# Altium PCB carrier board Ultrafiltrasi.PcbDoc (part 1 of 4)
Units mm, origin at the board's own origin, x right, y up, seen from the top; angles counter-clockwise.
Board outline 196.34 x 220.85 mm, 2 copper layers (Top Layer, Bottom Layer); 114 components, 209 nets, 667 pads, 70 vias.
Unrouted connection lines stored in the file: 5.
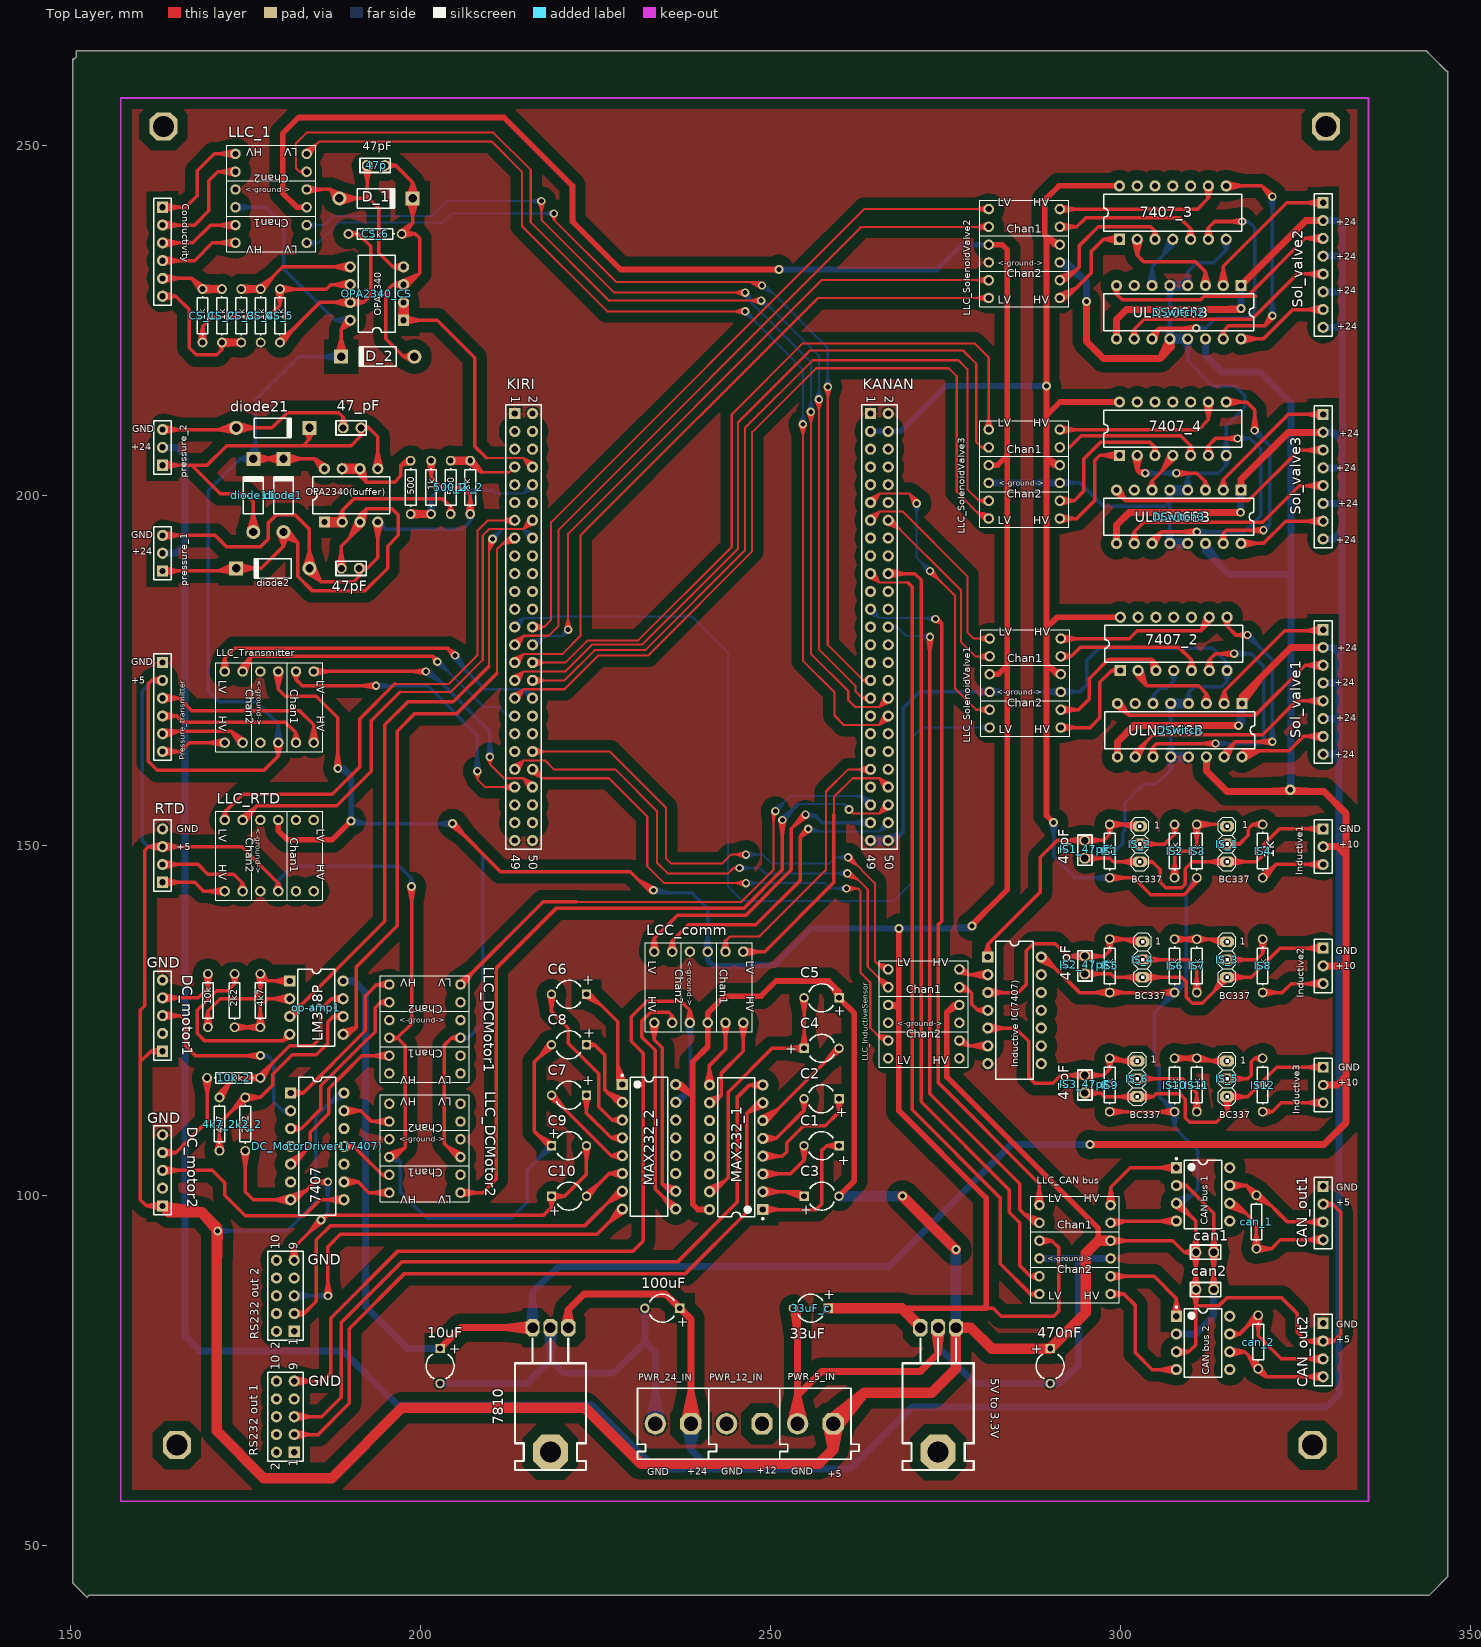
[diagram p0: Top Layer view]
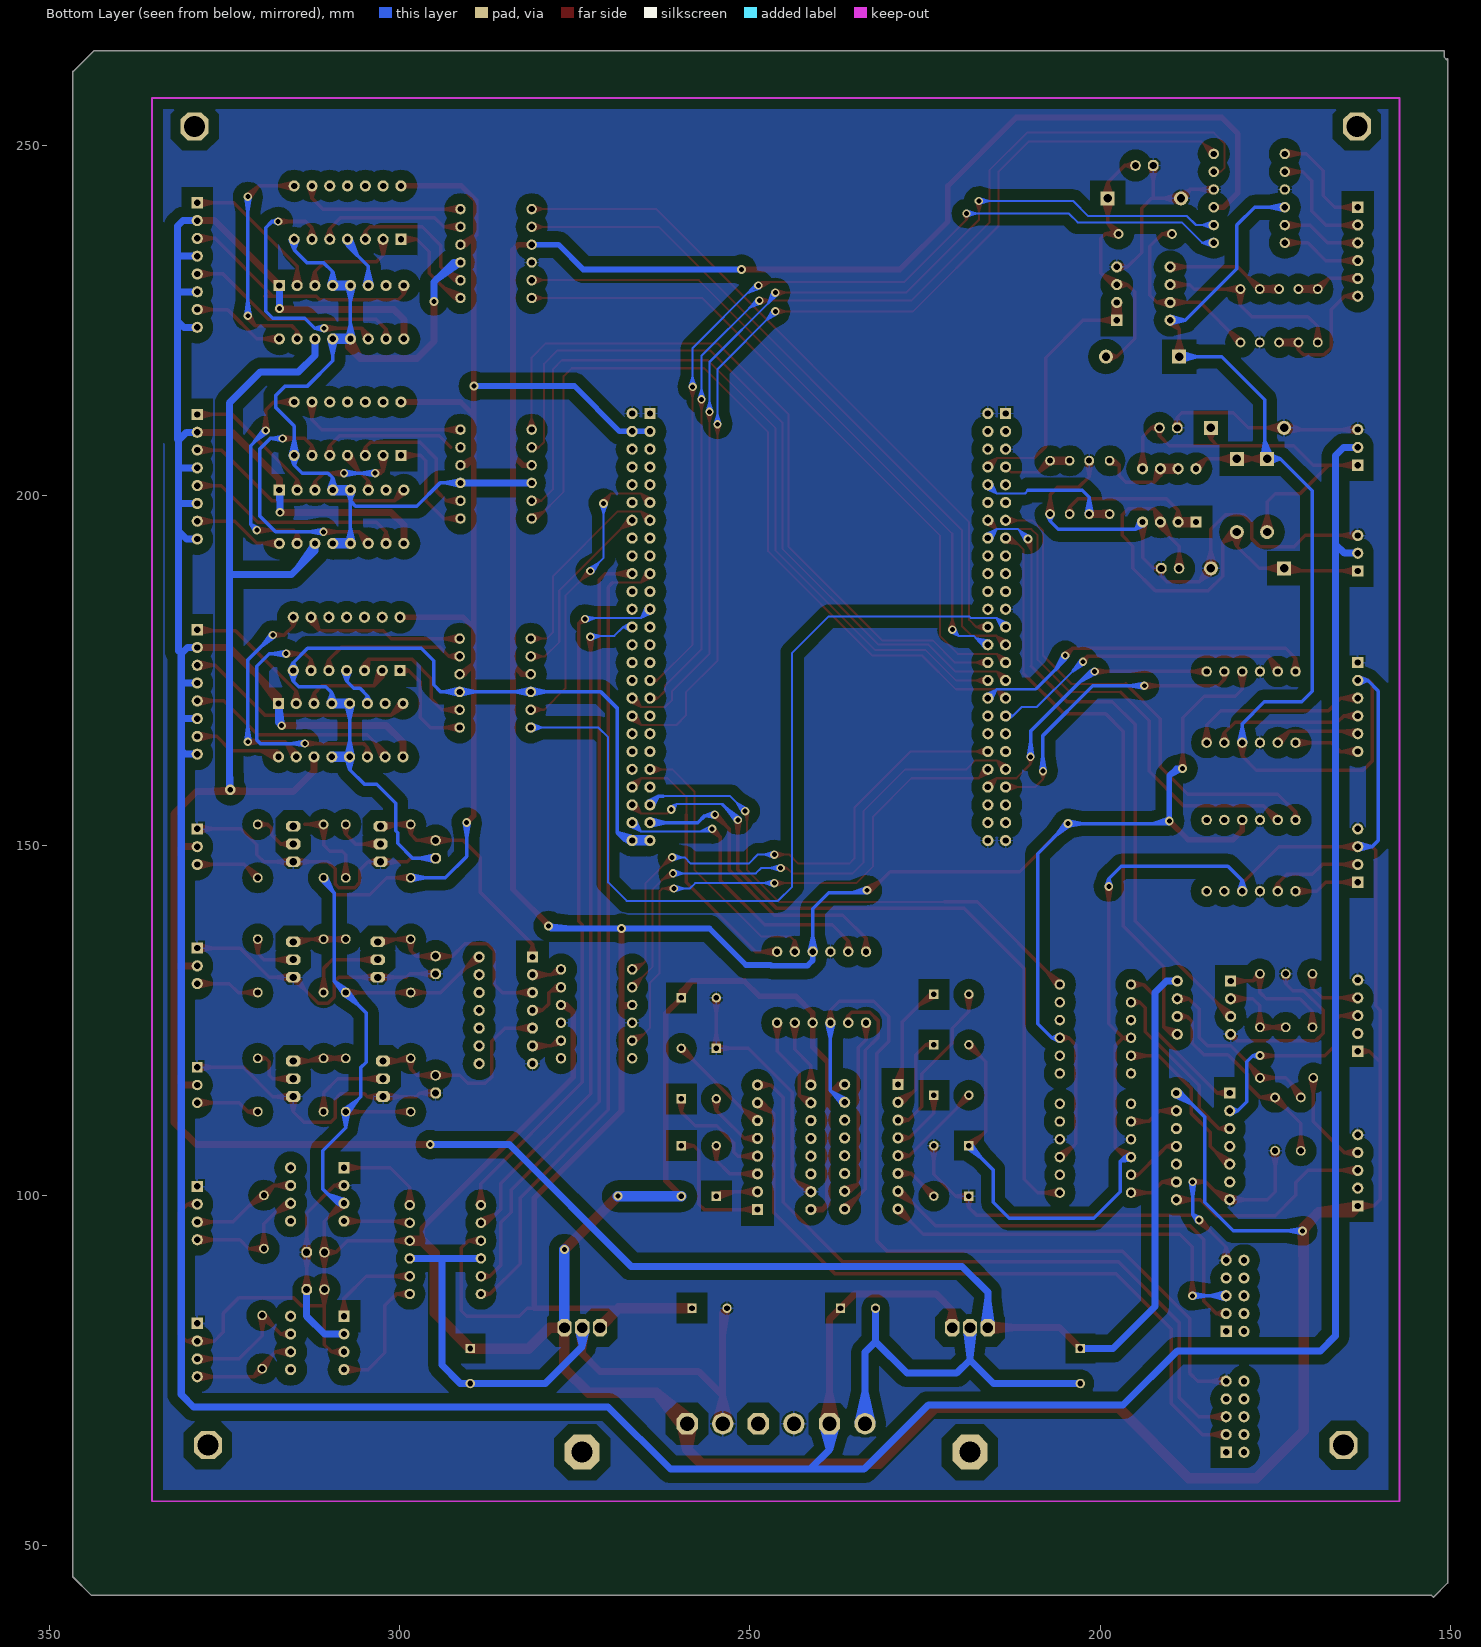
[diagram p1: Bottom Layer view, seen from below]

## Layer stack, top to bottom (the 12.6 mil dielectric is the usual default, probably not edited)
Top Solder: solder mask 0.0102, Solder Resist, Dk 3.5
Top Layer: signal copper 0.0356
Dielectric 1: dielectric 0.32, FR-4, Dk 4.8
Bottom Layer: signal copper 0.0356
Bottom Solder: solder mask 0.0102, Solder Resist, Dk 3.5

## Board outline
150.368,262.382 150.368,44.704 152.4,42.672 152.654,42.926 342.646,42.926 344.043,42.926 346.71,45.593 346.71,260.604 346.583,260.604 344.424,262.763 343.662,263.525 150.876,263.525 150.876,262.636 150.495,262.255

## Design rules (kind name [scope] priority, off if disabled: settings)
Clearance [All] p1: gap=0.3
PolygonConnect [All] p1: connectstyle=Relief reliefconductorwidth=0.254 reliefentries=4 polygonreliefangle="90 Angle" airgapwidth=0.254
RoutingVias [All] p1: holewidth=0.711 width=1.27 viastyle="Through Hole" minholewidth=0.711 minwidth=1.27 maxholewidth=0.711 maxwidth=1.27
SolderMaskExpansion [All] p1: expansion=0.102
Width [All] p1: maxlimit=2 minlimit=0.3 preferedwidth=0.5 minimp=50.000000 maximp=50.000000 favimp=50.000000
29 further rules are at their usual default settings.

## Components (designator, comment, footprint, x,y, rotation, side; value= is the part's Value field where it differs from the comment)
1k "Res1" AXIAL-0.3#1 201.549,201.168 r270 top
1k_2 "1k" AXIAL-0.3#1 207.137,201.168 r90 top
2k2 "Res1" AXIAL-0.3#2 173.482,127.889 r270 top
2k2_2 "2k2" AXIAL-0.3#2 175.006,110.236 r90 top
4k7 "Res1" AXIAL-0.3#2 177.165,127.889 r90 top
4k7_2 "4k7" AXIAL-0.3#2 171.323,110.236 r90 top
"5V to 3.3V" "7805" My_TO-220 276.479,81.153 r180 top
10k "Res1" AXIAL-0.3#2 169.672,127.889 r90 top
10k_2 "10k" AXIAL-0.3#2 173.355,116.84 r180 top
10uF "Cap2" CAPR5-4X5 202.819,75.692 r270 top
33uF_c "33uF" CAPR5-4X5 255.778,83.947 r180 top
47_pF "Cap" My_cap100n 190.246,209.677 r0 top
47p "47pF" My_cap100n 193.675,247.142 r0 top
47pF "Cap" My_cap100n 189.992,189.611 r180 top
100uF "Cap2" CAPR5-4X5 234.569,83.947 r180 top
470nF "Cap2" CAPR5-4X5 289.941,75.692 r270 top
500 "Res1" AXIAL-0.3#1 198.628,201.168 r90 top
500_2 "500" AXIAL-0.3#1 204.343,201.168 r270 top
7407_2 "7407" 646-06 307.594,178.816 r0 top
7407_3 "7407" 646-06 307.467,240.411 r0 top
7407_4 "7407" 646-06 307.467,209.55 r0 top
7810 "7805" My_TO-220 221.107,81.153 r180 top
C1 "Cap2" CAPR5-4X5 257.302,107.156 r180 top
C2 "Cap2" CAPR5-4X5 257.302,113.855 r180 top
C3 "Cap2" CAPR5-4X5 257.302,99.949 r0 top
C4 "Cap2" CAPR5-4X5 257.302,121.063 r0 top
C5 "Cap2" CAPR5-4X5 257.302,128.27 r180 top
C6 "Cap2" CAPR5-4X5 221.234,128.778 r180 top
C7 "Cap2" CAPR5-4X5 221.234,114.364 r180 top
C8 "Cap2" CAPR5-4X5 221.234,121.571 r180 top
C9 "Cap2" CAPR5-4X5 221.234,107.156 r0 top
C10 "Cap2" CAPR5-4X5 221.234,99.949 r0 top
can1 "Cap" My_cap100n 312.039,91.948 r180 top
can2 "Cap" My_cap100n 312.039,86.614 r180 top
"CAN bus 1" "MCP2551-I/P" PDIP300-P8 311.785,100.203 r0 top
"CAN bus 2" "MCP2551-I/P" PDIP300-P8 311.785,78.994 r0 top
can_1 "Res1" AXIAL-0.3#2 319.405,96.266 r90 top
can_2 "Res1" AXIAL-0.3#2 319.659,79.121 r90 top
CAN_out1 "Header 4" HDR1X4 328.93,101.346 r270 top
CAN_out2 "Header 4" HDR1X4 328.93,81.788 r270 top
Conductivity "Header 6" HDR1X6 163.195,241.173 r270 top
CS_1 "1k" AXIAL-0.3#2 168.91,225.679 r270 top
CS_2 "1k" AXIAL-0.3#2 171.672,225.679 r90 top
CS_3 "1k" AXIAL-0.3#2 174.434,225.679 r90 top
CS_4 "1k" AXIAL-0.3#2 177.197,225.679 r90 top
CS_5 "1k" AXIAL-0.3#2 179.959,225.679 r270 top
CS_6 "1k" AXIAL-0.3#2 193.548,237.363 r0 top
D_1 "1N4001" DO-41 193.675,242.443 r0 top
D_2 "1N4001" DO-41 193.929,219.837 r180 top
DC_motor1 "Header 5" HDR1X5 163.195,120.65 r90 top
DC_motor2 "Header 5" HDR1X5 163.195,98.552 r90 top
DC_MotorDriver1(7407) "7407" 646-06 185.293,107.061 r270 top
diode1 "1N4001" DO-41 180.467,200.025 r90 top
diode2 "1N4001" DO-41 178.943,189.611 r180 top
diode11 "1N4001" DO-41 176.149,200.025 r90 top
diode21 "1N4001" DO-41 178.943,209.677 r0 top
DSwitch "ULN2068B" 648C-02 308.444,166.497 r180 top
DSwitch2 "ULN2068B" 648C-02 308.317,226.187 r180 top
DSwitch3 "ULN2068B" 648C-02 308.317,196.977 r180 top
Inductive1 "Header 3" HDR1X3#1 328.93,152.4 r270 top
Inductive2 "Header 3" HDR1X3#1 328.93,135.382 r270 top
Inductive3 "Header 3" HDR1X3#2 328.93,118.364 r270 top
"Inductive IC(7407)" "SN74LS14N" 646-06 284.861,126.492 r270 top
IS1 "1k" AXIAL-0.3#2 298.45,149.225 r90 top
IS1_47pF "47pF" My_cap100n 294.894,149.479 r90 top
IS2 "1k" AXIAL-0.3#2 307.721,149.225 r270 top
IS2_47pF "47pF" My_cap100n 294.894,132.969 r90 top
IS3 "1k" AXIAL-0.3#2 310.896,149.225 r90 top
IS3_47pF "47pF" My_cap100n 294.894,115.951 r90 top
IS4 "1k" AXIAL-0.3#2 320.294,149.225 r270 top
IS5 "1k" AXIAL-0.3#2 298.45,132.842 r90 top
IS6 "1k" AXIAL-0.3#2 307.721,132.842 r90 top
IS7 "1k" AXIAL-0.3#2 310.896,132.842 r90 top
IS8 "1k" AXIAL-0.3#2 320.294,132.842 r270 top
IS9 "1k" AXIAL-0.3#2 298.45,115.824 r90 top
IS10 "1k" AXIAL-0.3#2 307.721,115.824 r90 top
IS11 "1k" AXIAL-0.3#2 310.896,115.824 r90 top
IS12 "1k" AXIAL-0.3#2 320.294,115.824 r270 top
IS_1 "BC337" My_1X03 315.214,150.241 r270 top
IS_2 "BC337" My_1X03 302.768,150.241 r270 top
IS_3 "BC337" My_1X03 315.214,133.731 r270 top
IS_4 "BC337" My_1X03 303.149,133.731 r270 top
IS_5 "BC337" My_1X03 315.214,116.713 r270 top
IS_6 "BC337" My_1X03 302.387,116.713 r270 top
KANAN "KANAN" HDR2X25 264.287,211.709 r270 top
KIRI "KIRI" HDR2X25 213.487,211.709 r270 top
LCC_comm "Logic Level Converter (3.3v - 5v) /  /  / https://www.sparkfun.com/products/8745" LOGIC_LEVEL_CONVERTER 232.156,136.144 r270 top
LLC_1 "Logic Level Converter (3.3v - 5v) /  /  / https://www.sparkfun.com/products/8745" LOGIC_LEVEL_CONVERTER 185.039,250.063 r180 top
"LLC_CAN bus" "Logic Level Converter (3.3v - 5v) /  /  / https://www.sparkfun.com/products/8745" LOGIC_LEVEL_CONVERTER 287.147,84.709 r0 top
LLC_DCMotor1 "Logic Level Converter (3.3v - 5v) /  /  / https://www.sparkfun.com/products/8745" LOGIC_LEVEL_CONVERTER 207.01,131.445 r180 top
LLC_DCMotor2 "Logic Level Converter (3.3v - 5v) /  /  / https://www.sparkfun.com/products/8745" LOGIC_LEVEL_CONVERTER 207.01,114.427 r180 top
LLC_InductiveSensor "Logic Level Converter (3.3v - 5v) /  /  / https://www.sparkfun.com/products/8745" LOGIC_LEVEL_CONVERTER 265.557,118.364 r0 top
LLC_RTD "Logic Level Converter (3.3v - 5v) /  /  / https://www.sparkfun.com/products/8745" LOGIC_LEVEL_CONVERTER 170.815,154.94 r270 top
LLC_SolenoidValve1 "Logic Level Converter (3.3v - 5v) /  /  / https://www.sparkfun.com/products/8745" LOGIC_LEVEL_CONVERTER 280.035,165.608 r0 top
LLC_SolenoidValve2 "Logic Level Converter (3.3v - 5v) /  /  / https://www.sparkfun.com/products/8745" LOGIC_LEVEL_CONVERTER 279.908,226.949 r0 top
LLC_SolenoidValve3 "Logic Level Converter (3.3v - 5v) /  /  / https://www.sparkfun.com/products/8745" LOGIC_LEVEL_CONVERTER 279.908,195.453 r0 top
LLC_Transmitter "Logic Level Converter (3.3v - 5v) /  /  / https://www.sparkfun.com/products/8745" LOGIC_LEVEL_CONVERTER 170.815,176.149 r270 top
MAX232_1 "MAX232ACPE" PE16A 245.11,106.934 r180 top
MAX232_2 "MAX232ACPE" PE16A 232.664,107.002 r0 top
op-amp1 "LM358P" P008 185.166,126.873 r270 top
OPA2340(buffer) "LM358P" P008 190.119,200.025 r0 top
OPA2340_CS "OPA2340" P008 193.802,228.854 r90 top
pressure_1 "Header 3" HDR1X3#1 163.195,189.23 r90 top
pressure_2 "Header 3" HDR1X3#1 163.195,204.343 r90 top
Pressure_transmitter "Header 6" HDR1X6 163.195,176.149 r270 top
PWR_5_IN "CON2 pin blue" My_CN2 261.493,62.357 r180 top
PWR_12_IN "CON2 pin blue" My_CN2 251.333,62.357 r180 top
PWR_24_IN "CON2 pin blue" My_CN2 241.173,62.357 r180 top
"RS232 out 1" "Header 5X2" HDR2X5 181.991,63.373 r90 top
"RS232 out 2" "Header 5X2" HDR2X5 181.991,80.645 r90 top
RTD "Header 4" HDR1X4 163.195,144.78 r90 top
Sol_valve1 "Header 8" HDR1X8 328.93,180.848 r270 top
Sol_valve2 "Header 8" HDR1X8 328.93,241.808 r270 top
Sol_valve3 "Header 8" HDR1X8 328.93,211.582 r270 top

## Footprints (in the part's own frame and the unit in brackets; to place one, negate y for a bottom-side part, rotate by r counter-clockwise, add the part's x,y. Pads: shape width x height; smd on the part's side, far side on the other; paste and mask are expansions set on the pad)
646-06 [mm] "DIP; 14 Leads; Row Spacing 7.62 mm; Pitch 2.54 mm"
  rect 1.6x1.6 hole 0.9 mask+0.102: 1(-7.62,-3.81)
  round 1.6 hole 0.9 mask+0.102: 2(-5.08,-3.81) 3(-2.54,-3.81) 4(0,-3.81) 5(2.54,-3.81) 6(5.08,-3.81) 7(7.62,-3.81) 8(7.62,3.81) 9(5.08,3.81) 10(2.54,3.81) 11(0,3.81) 12(-2.54,3.81) 13(-5.08,3.81) 14(-7.62,3.81)
  silkscreen extent -9.85,-2.65 9.85,2.65
648C-02 [mm] "DIP; 16 Leads; Row Spacing 7.62 mm; Pitch 2.54 mm"
  rect 1.6x1.6 hole 0.9 mask+0.102: 1(-8.89,-3.81)
  round 1.6 hole 0.9 mask+0.102: 2(-6.35,-3.81) 3(-3.81,-3.81) 4(-1.27,-3.81) 5(1.27,-3.81) 6(3.81,-3.81) 7(6.35,-3.81) 8(8.89,-3.81) 9(8.89,3.81) 10(6.35,3.81) 11(3.81,3.81) 12(1.27,3.81) 13(-1.27,3.81) 14(-3.81,3.81) 15(-6.35,3.81) 16(-8.89,3.81)
  silkscreen extent -10.7,-2.65 10.7,2.65
AXIAL-0.3#1 [mm] "Axial Device, Thru-Hole; 2 Leads; 0.3 in Pin Spacing"
  round 1.4 hole 0.85: 1(-3.81,0) 2(3.81,0)
  silkscreen extent -2.77,-0.76 2.77,0.76
AXIAL-0.3#2 [mm] "Axial Device, Thru-Hole; 2 Leads; 0.3 in Pin Spacing"
  round 1.4 hole 0.9: 1(-3.81,0) 2(3.81,0)
  silkscreen extent -2.77,-0.76 2.77,0.76
CAPR5-4X5 [mm] "Capacitor; 2 Leads"
  rect 1.35x1.35 hole 0.8: 1(-2.5,0)
  round 1.35 hole 0.8: 2(2.5,0)
  silkscreen extent -1.69,-2 1.82,2
DO-41 [mm] "Diode, Axial; Body 5.2 x 2.7 mm (LxDia. max), Lead Dia. 0.86 mm (max)"
  round 2 hole 1.2: 1(-5.23,0)
  rect 2x2 hole 1.2: 2(5.23,0)
  silkscreen extent -2.65,-1.4 2.75,1.4
HDR1X3#1 [mm] "Connector; Header; 3 Position"
  rect 1.6x1.6 hole 0.9 mask+0.102: 1(0,0)
  round 1.6 hole 0.9 mask+0.102: 2(2.54,0) 3(5.08,0)
  silkscreen extent -1.27,-1.27 6.35,1.27
HDR1X3#2 [mm] "Connector; Header; 3 Position"
  rect 1.5x1.5 hole 0.9: 1(0,0)
  round 1.5 hole 0.9: 2(2.54,0) 3(5.08,0)
  silkscreen extent -1.27,-1.27 6.35,1.27
HDR1X4 [mm] "Connector; Header; 4 Position"
  rect 1.6x1.6 hole 0.9 mask+0.102: 1(0,0)
  round 1.6 hole 0.9 mask+0.102: 2(2.54,0) 3(5.08,0) 4(7.62,0)
  silkscreen extent -1.27,-1.27 8.89,1.27
HDR1X5 [mm] "Connector; Header; 5 Position"
  rect 1.6x1.6 hole 0.9 mask+0.102: 1(0,0)
  round 1.6 hole 0.9 mask+0.102: 2(2.54,0) 3(5.08,0) 4(7.62,0) 5(10.16,0)
  silkscreen extent -1.27,-1.27 11.43,1.27
HDR1X6 [mm] "Connector; Header; 6 Position"
  rect 1.6x1.6 hole 0.9 mask+0.102: 1(0,0)
  round 1.6 hole 0.9 mask+0.102: 2(2.54,0) 3(5.08,0) 4(7.62,0) 5(10.16,0) 6(12.7,0)
  silkscreen extent -1.27,-1.27 13.97,1.27
HDR1X8 [mm] "Connector; Header; 8 Position"
  rect 1.6x1.6 hole 0.9 mask+0.102: 1(0,0)
  round 1.6 hole 0.9 mask+0.102: 2(2.54,0) 3(5.08,0) 4(7.62,0) 5(10.16,0) 6(12.7,0) 7(15.24,0) 8(17.78,0)
  silkscreen extent -1.27,-1.27 19.05,1.27
HDR2X5 [mm] "Connector; Header; 5x2 Position"
  rect 1.6x1.6 hole 0.9 mask+0.102: 1(0,0)
  round 1.6 hole 0.9 mask+0.102: 2(0,2.54) 3(2.54,0) 4(2.54,2.54) 5(5.08,0) 6(5.08,2.54) 7(7.62,0) 8(7.62,2.54) 9(10.16,0) 10(10.16,2.54)
  silkscreen extent -1.27,-1.27 11.43,3.81
HDR2X25 [mm] "Connector; Header; 25x2 Position"
  rect 1.6x1.6 hole 0.9 mask+0.102: 1(0,0)
  round 1.6 hole 0.9 mask+0.102: 2(0,2.54) 3(2.54,0) 4(2.54,2.54) 5(5.08,0) 6(5.08,2.54) 7(7.62,0) 8(7.62,2.54) 9(10.16,0) 10(10.16,2.54) 11(12.7,0) 12(12.7,2.54) 13(15.24,0) 14(15.24,2.54) 15(17.78,0) 16(17.78,2.54) 17(20.32,0) 18(20.32,2.54) 19(22.86,0) 20(22.86,2.54) 21(25.4,0) 22(25.4,2.54) 23(27.94,0) 24(27.94,2.54) 25(30.48,0) 26(30.48,2.54) 27(33.02,0) 28(33.02,2.54) 29(35.56,0) 30(35.56,2.54) 31(38.1,0) 32(38.1,2.54) 33(40.64,0) 34(40.64,2.54) 35(43.18,0) 36(43.18,2.54) 37(45.72,0) 38(45.72,2.54) 39(48.26,0) 40(48.26,2.54) 41(50.8,0) 42(50.8,2.54) 43(53.34,0) 44(53.34,2.54) 45(55.88,0) 46(55.88,2.54) 47(58.42,0) 48(58.42,2.54) 49(60.96,0) 50(60.96,2.54)
  silkscreen extent -1.27,-1.27 62.23,3.81
LOGIC_LEVEL_CONVERTER [mm]
  round 1.5 hole 0.9: P$1(1.27,13.97) P$2(1.27,11.43) P$3(1.27,8.89) P$4(1.27,6.35) P$5(1.27,3.81) P$6(1.27,1.27) P$7(11.43,1.27) P$8(11.43,3.81) P$9(11.43,6.35) P$10(11.43,8.89) P$11(11.43,11.43) P$12(11.43,13.97)
  silkscreen extent 0,0 12.7,15.24
My_1X03 [mil]
  oct 60x80 hole 40: 1(-100,0) 2(0,0) 3(100,0)
  silkscreen extent -150,-50 150,50
My_cap100n [mil]
  oct 60x60 hole 40: 1(-50,0)
  round 60 hole 40: 2(50,0)
  silkscreen extent -90,-40 80,40
My_CN2 [mil]
  oct 120x120 hole 80: 1(99.5,-200.5)
  round 120 hole 80: 2(299.5,-200.5)
  silkscreen extent -45,-400 400,0
My_TO-220 [mil]
  oct 196.85x196.85 hole 118.11: 0(99.49,699.49)
  oct 80x100 hole 60: 1(-0.5,-0.5) 2(99.5,-0.5) 3(199.5,-0.5)
  silkscreen extent -101,60 300,800
P008 [mm] "DIP; 8 Leads; Row Spacing 7.62 mm; Pitch 2.54 mm"
  rect 1.6x1.6 hole 0.9 mask+0.102: 1(-3.81,-3.81)
  round 1.6 hole 0.9 mask+0.102: 2(-1.27,-3.81) 3(1.27,-3.81) 4(3.81,-3.81) 5(3.81,3.81) 6(1.27,3.81) 7(-1.27,3.81) 8(-3.81,3.81)
  silkscreen extent -5.5,-2.65 5.5,2.65
PDIP300-P8 [mm] "DIP, 8-Leads, Row Spacing 7.62mm, Pitch 2.54mm, Body 9.5x6.6mm"
  rect 1.6x1.6 hole 0.9 mask+0.102: 1(-3.81,3.81)
  round 1.6 hole 0.9 mask+0.102: 2(-3.81,1.27) 3(-3.81,-1.27) 4(-3.81,-3.81) 5(3.81,-3.81) 6(3.81,-1.27) 7(3.81,1.27) 8(3.81,3.81)
  silkscreen extent -3.93,-4.9 2.65,5.23, body extent -3.55,-4.9 3.55,4.9, height 5.34
PE16A [mm] "DIP, 16-Leads, Row Spacing 7.62mm, Pitch 2.54mm, Body 19.18x6.99mm"
  rect 1.6x1.6 hole 0.9 mask+0.102: 1(-3.81,8.89)
  round 1.6 hole 0.9 mask+0.102: 2(-3.81,6.35) 3(-3.81,3.81) 4(-3.81,1.27) 5(-3.81,-1.27) 6(-3.81,-3.81) 7(-3.81,-6.35) 8(-3.81,-8.89) 9(3.81,-8.89) 10(3.81,-6.35) 11(3.81,-3.81) 12(3.81,-1.27) 13(3.81,1.27) 14(3.81,3.81) 15(3.81,6.35) 16(3.81,8.89)
  silkscreen extent -3.94,-9.9 2.65,10.31, body extent -3.3,-9.9 3.3,9.9, height 5.08

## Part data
1k 2k2 4k7 10k 500 can_1 can_2: "Resistor"
1k_2 2k2_2 4k7_2 10k_2 500_2 CS_1 CS_2 CS_3 CS_4 CS_5 CS_6 IS1 IS2 IS3 IS4 IS5 IS6 IS7 IS8 IS9 IS10 IS11 IS12: library part Res1, "Resistor"
"5V to 3.3V" 7810: "Regulator"
10uF 100uF 470nF C1 C2 C3 C4 C5 C6 C7 C8 C9 C10: "Capacitor"
33uF_c: library part Cap2, "Capacitor"
47_pF 47p 47pF can1 can2 IS1_47pF IS2_47pF IS3_47pF: library part "Cap ceramic", "CAP-100Nf"
7407_2 7407_3 7407_4 DC_MotorDriver1(7407): library part SN74LS14N, "Hex Schmitt-Trigger Inverter"
"CAN bus 1" "CAN bus 2": "High-Speed CAN Transceiver, 8-Pin PDIP, Industrial Temperature"
CAN_out1 CAN_out2 RTD: "Header, 4-Pin"
Conductivity Pressure_transmitter: "Header, 6-Pin"
D_1 D_2 diode1 diode2 diode11 diode21: library part "Diode 1N4001", "1 Amp General Purpose Rectifier"
DC_motor1 DC_motor2: "Header, 5-Pin"
DSwitch DSwitch2 DSwitch3: "Quad 1.5A Darlington Switch"
Inductive1 Inductive2 Inductive3 pressure_1 pressure_2: "Header, 3-Pin"
"Inductive IC(7407)": "Hex Schmitt-Trigger Inverter"
IS_1 IS_2 IS_3 IS_4 IS_5 IS_6: "Transistor, NPN, 300MHz, 40V, 200mA, SOT-23 pkg"
KANAN KIRI: library part "Header 25X2", "Header, 25-Pin, Dual row"
LCC_comm LLC_1 "LLC_CAN bus" LLC_DCMotor1 LLC_DCMotor2 LLC_InductiveSensor LLC_RTD LLC_SolenoidValve1 LLC_SolenoidValve2 LLC_SolenoidValve3 LLC_Transmitter: library part LOGIC_LEVEL_CONVERTER
MAX232_1 MAX232_2: "+5V Powered, Multi-Channel RS-232 Driver/Receiver"
op-amp1 OPA2340(buffer): "Dual Operational Amplifier"
OPA2340_CS: library part LM358P, "Dual Operational Amplifier"
PWR_5_IN PWR_12_IN PWR_24_IN: "Connector blue screw"
"RS232 out 1" "RS232 out 2": "Header, 5-Pin, Dual row"
Sol_valve1 Sol_valve2 Sol_valve3: "Header, 8-Pin"

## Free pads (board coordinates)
  oct 4x4 hole 3: 0(329.311,252.73) 1(163.322,252.73) 2(165.227,64.389) 3(327.406,64.389)

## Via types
v1: diameter 1.2, hole 0.711, Top Layer to Bottom Layer, 26 vias
v2: diameter 1.27, hole 0.711, Top Layer to Bottom Layer, 24 vias
v3: diameter 1.2, hole 0.7, Top Layer to Bottom Layer, 19 vias
v4: diameter 1.5, hole 0.8, Top Layer to Bottom Layer, 1 vias

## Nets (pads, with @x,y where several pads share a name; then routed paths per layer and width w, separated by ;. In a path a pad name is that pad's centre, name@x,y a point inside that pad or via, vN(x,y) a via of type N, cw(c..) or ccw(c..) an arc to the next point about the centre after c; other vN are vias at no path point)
DINPLC1: Conductivity.4 LLC_1.P$12 | length 20.6
  Top Layer w0.5: Conductivity.4@163.195,233.553 167.767,233.553 170.307,236.093 LLC_1.P$12@173.609,236.093 ; Conductivity.4@163.261,233.007 165.495,233.553 Conductivity.4@163.261,234.099 ; LLC_1.P$12@173.553,235.596 171.359,236.093 LLC_1.P$12@173.553,236.59
DOPLC1: Conductivity.1 LLC_1.P$7 | length 24.8
  Top Layer w0.5: Conductivity.1@163.195,241.173 166.497,241.173 168.148,242.824 168.148,246.38 170.561,248.793 LLC_1.P$7@173.609,248.793 ; Conductivity.1@163.261,240.627 165.495,241.173 Conductivity.1@163.261,241.719 ; LLC_1.P$7@173.553,248.296 171.359,248.793 LLC_1.P$7@173.553,249.29
DOPLC2: Conductivity.2 LLC_1.P$8 | length 27.4
  Top Layer w0.5: Conductivity.2@163.195,238.633 167.767,238.633 169.799,240.665 169.799,244.983 171.069,246.253 LLC_1.P$8@173.609,246.253 171.359,246.253 ; Conductivity.2@163.261,238.087 165.495,238.633 Conductivity.2@163.261,239.179 ; LLC_1.P$8@173.553,245.756 171.359,246.253 ; LLC_1.P$8@173.553,246.75 171.359,246.253
DOPLC3: Conductivity.3 LLC_1.P$11 | length 20.6
  Top Layer w0.5: Conductivity.3@163.195,236.093 167.513,236.093 170.053,238.633 LLC_1.P$11@173.609,238.633 ; Conductivity.3@163.261,235.547 165.495,236.093 Conductivity.3@163.261,236.639 ; LLC_1.P$11@173.553,238.136 171.359,238.633 LLC_1.P$11@173.553,239.13
DTR_5V: LLC_Transmitter.P$11 Pressure_transmitter.4 | length 28.3
  Top Layer w0.5: Pressure_transmitter.4@163.195,168.529 165.227,168.529 ; Pressure_transmitter.4@163.269,167.984 165.227,168.529 ; Pressure_transmitter.4@163.269,169.074 165.227,168.529 ; LLC_Transmitter.P$11@181.753,164.808 182.245,166.116 ; LLC_Transmitter.P$11@182.245,164.719 182.245,166.116 ; LLC_Transmitter.P$11@182.737,164.808 182.245,166.116 ; 165.227,168.529 166.116,167.64 180.721,167.64 182.245,166.116
GND: 1k.1 1k_2.1 2k2.1 2k2_2.1 10uF.2 33uF_c.2 47_pF.1 47p.1 47pF.1 100uF.2 470nF.2 7407_2.7 7407_3.7 7407_4.7 7810.2 "5V to 3.3V.2" "CAN bus 1.2" "CAN bus 2.2" "Inductive IC(7407).7" "LLC_CAN bus.P$4" "LLC_CAN bus.P$9" "RS232 out 1.9" "RS232 out 2.9" C4.1 C5.2 C9.2 C10.1 can1.1 can2.1 CAN_out1.1 CAN_out2.1 CS_4.1 D_1.1 DC_motor1.5 DC_motor2.5 DC_MotorDriver1(7407).7 diode2.1 diode21.1 DSwitch2.4 DSwitch2.5 DSwitch2.12 DSwitch2.13 DSwitch3.4 DSwitch3.5 DSwitch3.12 DSwitch3.13 DSwitch.4 DSwitch.5 DSwitch.12 DSwitch.13 Inductive1.1 Inductive2.1 Inductive3.1 IS1_47pF.1 IS2_47pF.1 IS3_47pF.1 IS_1.3 IS_2.3 IS_3.3 IS_4.3 IS_5.3 IS_6.3 KANAN.1 KANAN.2 KANAN.49 KANAN.50 KIRI.1 KIRI.2 KIRI.5 KIRI.23 KIRI.49 KIRI.50 LCC_comm.P$4 LCC_comm.P$9 LLC_1.P$4 LLC_1.P$9 LLC_DCMotor2.P$4 LLC_DCMotor2.P$9 LLC_InductiveSensor.P$4 LLC_InductiveSensor.P$9 LLC_RTD.P$4 LLC_RTD.P$9 LLC_SolenoidValve1.P$4 LLC_SolenoidValve1.P$9 LLC_SolenoidValve2.P$4 LLC_SolenoidValve2.P$9 LLC_SolenoidValve3.P$4 LLC_SolenoidValve3.P$9 LLC_Transmitter.P$4 LLC_Transmitter.P$9 MAX232_1.15 MAX232_2.15 op-amp1.4 OPA2340(buffer).4 OPA2340_CS.4 pressure_1.3 pressure_2.3 Pressure_transmitter.1 PWR_5_IN.2 PWR_12_IN.2 PWR_24_IN.2 RTD.4 | length 1609.2
  Top Layer w0.5: pressure_1.3@163.195,194.31 170.688,194.31 172.339,192.659 177.165,192.659 178.308,193.802 178.308,196.088 179.451,197.231 182.118,197.231 184.173,195.176 diode2.1@184.173,189.611 ; pressure_2.3@163.195,209.423 173.482,209.423 173.736,209.677 178.816,209.677 180.975,211.836 188.341,211.836 188.976,211.201 ; pressure_1.3@163.261,193.764 165.495,194.31 pressure_1.3@163.261,194.856 ; pressure_2.3@163.261,208.877 165.495,209.423 pressure_2.3@163.261,209.969 ; 2k2.1@173.038,131.627 173.482,130.302 ; 2k2.1@173.482,131.699 173.482,130.302 ; diode21.1@173.529,210.404 171.179,209.423 ; diode21.1@173.676,209.924 171.179,209.423 ; diode21.1@173.677,208.928 171.179,209.423 ; diode21.1@173.725,209.927 176.213,209.677 ; diode21.1@173.825,208.935 176.213,209.677 ; diode21.1@173.825,210.419 176.213,209.677 ; 2k2.1@173.926,131.627 173.482,130.302 ; 2k2_2.1@174.558,106.38 175.006,104.226 2k2_2.1@175.454,106.38 ; 2k2_2.1@175.006,106.426 175.006,100.584 176.149,99.441 181.483,99.441 ; op-amp1.4@180.891,123.357 180.467,122.174 ; 181.246,99.937 183.763,100.832 ; 181.417,98.895 179.183,99.441 181.417,99.987 ; 181.447,90.886 181.991,92.672 ; op-amp1.4@181.65,122.598 180.467,122.174 ; 181.816,99.003 183.763,100.832 ; 181.991,73.533 186.055,73.533 187.222,74.7 187.222,82.536 196.737,92.051 230.354,92.051 231.857,93.554 231.857,120.351 230.148,122.061 230.148,125.589 232.321,127.762 237.236,127.762 238.506,126.492 ; 181.991,90.805 181.991,92.672 ; 182.057,72.987 184.291,73.533 182.057,74.079 ; 182.535,90.886 181.991,92.672 ; diode2.1@183.431,189.724 184.173,192.111 ; diode2.1@183.682,189.044 185.801,187.706 ; LLC_1.P$4@183.769,243.713 187.198,243.713 187.186,243.701 ; LLC_1.P$4@183.825,243.216 186.019,243.713 LLC_1.P$4@183.825,244.21 ; diode2.1@183.923,189.623 184.173,192.111 ; diode2.1@183.991,189.439 185.801,187.706 ; diode2.1@184.371,189.764 185.801,187.706 ; diode2.1@184.423,189.623 184.173,192.111 ; diode2.1@184.81,190.007 185.801,187.706 ; diode2.1@184.915,189.724 184.173,192.111 ; v2@185.545,96.77 184.143,94.824 ; v2@185.621,96.838 186.577,97.258 ; v2(185.839,96.52) 184.143,94.824 ; v2@186.088,96.227 184.143,94.824 ; v2@186.156,96.303 186.577,97.258 ; v3@186.759,101.633 184.912,101.981 ; v3@186.759,102.329 184.912,101.981 ; v3(186.792,101.981) 184.912,101.981 ; D_1.1@187.815,242.036 187.186,243.701 ; D_1.1@188.256,242.279 187.186,243.701 ; D_1.1@188.457,242.193 190.945,242.443 ; D_1.1@188.457,242.693 190.945,242.443 ; 47_pF.1@188.471,209.763 188.976,211.201 ; D_1.1@188.557,241.701 190.945,242.443 ; D_1.1@188.557,243.185 190.945,242.443 ; D_1.1@188.609,242.632 187.186,243.701 ; D_1.1@188.852,243.073 187.186,243.701 ; 47_pF.1@188.976,209.677 188.976,211.201 ; 47_pF.1@189.481,209.763 188.976,211.201 ; 47pF.1@190.763,189.496 191.262,188.468 ; 47pF.1@191.377,189.112 192.405,189.611 ; 47pF.1@191.377,190.11 192.405,189.611 ; 47pF.1@191.761,189.496 191.262,188.468 ; 47p.1@191.896,247.084 192.405,244.88 47p.1@192.914,247.084 ; 47p.1@192.405,247.142 192.405,242.697 192.659,242.443 ; 193.383,196.149 193.929,193.915 194.475,196.149 ; 193.929,196.215 193.929,191.135 192.405,189.611 ; OPA2340_CS.4@197.513,232.123 196.088,232.664 ; OPA2340_CS.4@197.513,233.205 196.088,232.664 ; OPA2340_CS.4@197.612,232.664 196.088,232.664 ; 1k.1@201.101,204.932 201.549,202.778 1k.1@201.997,204.932 ; 1k.1@201.549,204.978 201.549,202.692 203.073,201.168 206.121,201.168 207.137,200.152 1k_2.1@207.137,197.358 ; 1k_2.1@206.689,197.404 207.137,199.558 1k_2.1@207.585,197.404 ; C10.1@218.313,99.893 218.734,98.338 ; C10.1@218.782,99.527 220.599,99.949 ; C10.1@218.782,100.371 220.599,99.949 ; C10.1@219.155,99.893 218.734,98.338 ; C9.2@223.311,107.115 223.734,104.981 ; C9.2@224.157,107.115 223.734,104.981 ; LCC_comm.P$9@238.011,124.784 238.506,126.492 ; LCC_comm.P$9@238.506,124.714 238.506,126.492 ; LCC_comm.P$9@239.001,124.784 238.506,126.492 ; MAX232_1.15@241.032,101.065 243.442,102.091 ; MAX232_1.15@241.662,100.17 243.442,102.091 ; C4.1@254.379,121.104 254.802,123.238 C4.1@255.225,121.104 ; C5.2@254.379,128.228 254.802,126.095 C5.2@255.225,128.228 ; C4.1@254.76,120.64 252.627,121.063 ; C4.1@254.76,121.486 252.627,121.063 ; C5.2@254.802,128.27 C4.1@254.802,121.063 ; IS3_47pF.1@294.894,114.681 297.156,114.681 ; IS2_47pF.1@294.894,131.699 298.577,131.699 299.085,131.191 IS_4.3@303.149,131.191 308.737,131.191 309.372,130.556 309.372,128.397 310.261,127.508 311.658,127.508 315.214,131.064 IS_3.3@315.214,131.191 318.643,131.191 322.834,135.382 Inductive2.1@328.93,135.382 ; IS1_47pF.1@294.894,148.209 298.45,148.209 298.958,147.701 IS_2.3@302.768,147.701 304.546,147.701 ; IS3_47pF.1@294.952,114.172 297.156,114.681 ; IS3_47pF.1@294.952,115.19 297.156,114.681 ; IS2_47pF.1@294.952,131.19 297.156,131.699 IS2_47pF.1@294.952,132.208 ; IS1_47pF.1@294.952,147.7 297.156,148.209 IS1_47pF.1@294.952,148.718 ; IS_6.3@302.075,113.664 299.871,114.173 ; IS_6.3@302.075,114.682 299.871,114.173 ; IS_6.3@302.133,114.173 299.871,114.173 ; IS_2.3@302.456,147.192 300.252,147.701 ; IS_2.3@302.456,148.21 300.252,147.701 ; IS_2.3@302.514,147.701 300.252,147.701 ; IS_6.3@302.641,114.173 304.673,114.173 ; IS_6.3@302.706,113.665 304.673,114.173 ; IS_6.3@302.706,114.681 304.673,114.173 ; IS_4.3@302.837,130.682 300.633,131.191 ; IS_4.3@302.837,131.7 300.633,131.191 ; IS_4.3@302.895,131.191 300.633,131.191 ; IS_2.3@303.022,147.701 304.546,147.701 ; IS_2.3@303.108,147.196 304.546,147.701 ; IS_2.3@303.108,148.206 304.546,147.701 ; IS_4.3@303.403,131.191 305.665,131.191 ; IS_4.3@303.461,130.682 305.665,131.191 ; IS_4.3@303.461,131.7 305.665,131.191 ; 307.975,101.473 309.372,101.473 ; 308.083,100.934 309.372,101.473 ; 308.083,102.012 309.372,101.473 ; can2.1@312.8,86.672 313.309,88.876 can2.1@313.818,86.672 ; can1.1@312.8,91.89 313.309,89.686 can1.1@313.818,91.89 ; can1.1@312.8,92.006 313.309,94.21 can1.1@313.818,92.006 ; can2.1@313.309,86.614 can1.1@313.309,91.948 313.309,97.536 309.372,101.473 ; IS_3.3@314.528,131.465 313.466,129.316 ; IS_5.3@314.706,114.112 315.214,112.014 ; IS_1.3@314.902,147.192 312.698,147.701 ; IS_1.3@314.902,148.21 312.698,147.701 ; IS_3.3@314.96,131.191 313.466,129.316 ; IS_1.3@314.96,147.701 312.698,147.701 ; IS_3.3@315.324,130.831 313.466,129.316 ; IS_5.3@315.468,114.173 317.73,114.173 ; IS_3.3@315.468,131.191 317.73,131.191 ; IS_1.3@315.468,147.701 317.73,147.701 ; IS_5.3@315.526,113.664 317.73,114.173 ; IS_5.3@315.526,114.682 317.73,114.173 ; IS_3.3@315.526,130.682 317.73,131.191 ; IS_3.3@315.526,131.7 317.73,131.191 ; IS_1.3@315.526,147.192 317.73,147.701 ; IS_1.3@315.526,148.21 317.73,147.701 ; IS_5.3@315.722,114.112 315.214,112.014 ; Inductive2.1@328.864,134.836 326.63,135.382 Inductive2.1@328.864,135.928 ; Inductive1.1@328.864,151.854 326.63,152.4 Inductive1.1@328.864,152.946 ; Inductive3.1@328.874,117.867 326.68,118.364 Inductive3.1@328.874,118.861 ; Inductive3.1@328.93,118.364 322.326,118.364 318.135,114.173 IS_5.3@315.214,114.173 315.214,112.014 ; Inductive1.1@328.93,152.4 322.707,152.4 320.421,150.114 320.421,148.717 319.405,147.701 IS_1.3@315.214,147.701 310.261,147.701 309.245,146.685 309.245,144.526 308.737,144.018 306.451,144.018 305.689,144.78 305.689,146.558 304.546,147.701 ; 171.179,209.423 diode21.1@173.713,209.677 176.213,209.677 ; 171.179,209.423 173.726,209.427 176.213,209.677 ; 173.482,130.302 172.466,129.286 170.942,129.286 168.148,126.492 168.148,123.19 169.164,122.174 180.467,122.174 ; 180.467,122.174 op-amp1.4@181.356,123.063 180.467,122.174 ; 181.483,99.441 182.372,99.441 ; 181.483,99.441 183.763,100.832 ; 181.483,99.441 182.372,99.441 ; 181.991,92.672 186.577,97.258 ; 182.372,99.441 181.653,98.918 182.372,99.441 ; 182.372,99.441 181.653,99.964 182.372,99.441 ; 182.372,99.441 184.912,101.981 ; diode2.1@184.173,189.611 185.801,187.706 ; diode2.1@184.173,189.611 184.173,189.334 185.801,187.706 ; 185.801,187.706 190.5,187.706 191.262,188.468 ; 186.577,97.258 217.654,97.258 218.734,98.338 ; 187.186,243.701 D_1.1@188.445,242.443 192.659,242.443 ; 191.262,188.468 47pF.1@191.262,189.611 192.405,189.611 ; 192.659,242.443 194.056,241.046 194.056,234.696 196.088,232.664 ; 218.734,98.338 C10.1@218.734,99.949 220.599,99.949 ; 220.599,99.949 223.734,103.084 C9.2@223.734,107.156 223.734,104.981 ; 243.442,102.091 MAX232_1.15@241.3,100.584 241.935,100.584 243.967,102.616 243.967,114.808 250.222,121.063 C4.1@254.802,121.063 ; 252.627,121.063 C4.1@254.802,121.063 ; 297.156,114.681 297.664,114.173 IS_6.3@302.387,114.173 304.673,114.173 ; 304.673,114.173 305.054,114.554 308.483,114.554 309.245,113.792 309.245,111.125 309.88,110.49 313.69,110.49 315.214,112.014
  Top Layer w1: PWR_5_IN.2@252.87,67.579 253.886,71.501 ; PWR_5_IN.2@253.886,67.45 253.886,71.501 ; 253.886,80.06 33uF_c.2@253.278,83.947 253.886,83.339 253.886,71.501 ; PWR_5_IN.2@254.901,67.579 253.886,71.501 ; 273.437,80.873 273.952,77.483 ; 273.952,80.912 273.952,77.483 ; 273.952,81.166 273.952,77.483 ; 274.466,80.873 273.952,77.483 ; 295.148,224.076 v2(295.148,227.711) 295.148,221.996 297.567,219.577 305.667,219.577 ; DSwitch2.12@307.307,221.651 307.307,221.217 ; 253.886,71.501 257.315,74.93 271.399,74.93 273.952,77.483 ; 305.667,219.577 DSwitch2.12@307.047,222.377 ; 305.667,219.577 307.307,221.217 ; DSwitch2.12@307.047,222.377 307.307,221.217 ; DSwitch2.12@307.047,222.377 307.307,221.217
  Bottom Layer w0.5: v2@185.626,96.841 186.792,97.384 ; v2@185.801,96.393 186.792,97.384 ; v2(185.839,96.52) 186.792,97.384 ; v2@186.137,96.277 186.792,97.384 ; v3@186.443,101.952 186.792,99.881 v3@187.141,101.952 ; v3(186.792,101.981) 186.792,97.384 ; 193.622,195.759 194.945,195.199 ; 193.929,196.215 194.945,195.199 ; 194.385,196.522 194.945,195.199 ; 1k_2.1@206.698,197.258 207.137,196.342 ; 1k_2.1@207.137,197.358 207.137,196.342 ; 1k_2.1@207.576,197.258 207.137,196.342 ; MAX232_2.15@236.173,113.813 238.455,114.974 ; MAX232_2.15@236.866,112.966 238.455,114.974 ; LCC_comm.P$9@238.01,124.654 238.524,122.464 ; LCC_comm.P$9@239.003,124.662 238.524,122.464 ; KANAN.49@264.287,150.749 KANAN.50@266.827,150.749 ; KANAN.49@264.353,150.203 266.587,150.749 KANAN.49@264.353,151.295 ; KANAN.50@266.626,151.261 268.986,151.892 ; KANAN.50@266.647,150.229 KANAN.49@264.56,151.245 ; KANAN.50@266.647,151.269 KANAN.49@264.56,150.253 ; KANAN.50@266.761,150.203 264.527,150.749 KANAN.50@266.761,151.295 ; KANAN.50@266.88,150.202 KANAN.49@264.56,150.253 ; KANAN.50@266.88,151.296 KANAN.49@264.56,151.245 ; KANAN.50@267.137,150.295 268.986,151.892 ; LLC_SolenoidValve1.P$4@281.249,171.461 279.055,171.958 LLC_SolenoidValve1.P$4@281.249,172.455 ; LLC_SolenoidValve1.P$4@281.361,171.461 283.555,171.958 LLC_SolenoidValve1.P$4@281.361,172.455 ; LLC_SolenoidValve3.P$9@291.338,201.803 294.259,201.803 297.561,198.501 306.324,198.501 307.047,199.224 ; LLC_SolenoidValve3.P$9@291.394,201.306 293.588,201.803 LLC_SolenoidValve3.P$9@291.394,202.3 ; LLC_SolenoidValve1.P$9@291.409,171.461 289.215,171.958 LLC_SolenoidValve1.P$9@291.409,172.455 ; LLC_SolenoidValve1.P$9@291.521,171.461 293.715,171.958 LLC_SolenoidValve1.P$9@291.521,172.455 ; IS1_47pF.1@294.894,148.209 298.196,148.209 300.318,150.331 300.318,151.862 300.6,152.144 300.6,156.074 303.276,158.75 305.054,158.75 307.174,160.87 ; IS1_47pF.1@294.952,147.7 297.156,148.209 IS1_47pF.1@294.952,148.718 ; DSwitch3.12@306.501,193.233 307.047,195.467 DSwitch3.12@307.593,193.233 ; DSwitch2.12@306.501,222.443 307.047,224.677 DSwitch2.12@307.593,222.443 ; DSwitch2.5@306.501,229.931 307.047,227.697 DSwitch2.5@307.593,229.931 ; DSwitch3.5@306.506,200.69 307.047,199.224 ; DSwitch.12@306.628,162.753 307.174,164.987 DSwitch.12@307.72,162.753 ; DSwitch.5@306.628,170.241 307.174,168.007 DSwitch.5@307.72,170.241 ; DSwitch.12@306.63,162.604 307.174,160.87 ; DSwitch3.12@307.113,192.621 309.347,193.167 DSwitch3.12@307.113,193.713 ; DSwitch3.5@307.113,200.241 309.347,200.787 DSwitch3.5@307.113,201.333 ; DSwitch2.12@307.113,221.831 309.347,222.377 DSwitch2.12@307.113,222.923 ; DSwitch2.5@307.113,229.451 309.347,229.997 DSwitch2.5@307.113,230.543 ; DSwitch.12@307.24,162.141 309.474,162.687 DSwitch.12@307.24,163.233 ; DSwitch.5@307.24,169.761 309.474,170.307 DSwitch.5@307.24,170.853 ; DSwitch3.5@307.588,200.69 307.047,199.224 ; DSwitch.12@307.718,162.604 307.174,160.87 ; DSwitch2.13@309.041,222.311 309.587,220.077 DSwitch2.13@310.133,222.311 ; DSwitch2.4@309.043,230.075 309.587,231.941 ; DSwitch3.4@309.044,200.874 309.587,202.526 ; DSwitch.4@309.173,170.404 309.714,171.87 ; DSwitch3.13@309.407,192.647 DSwitch3.12@307.32,193.663 ; DSwitch3.13@309.407,193.687 DSwitch3.12@307.32,192.671 ; DSwitch3.4@309.407,200.267 DSwitch3.5@307.32,201.283 ; DSwitch3.4@309.407,201.307 DSwitch3.5@307.32,200.291 ; DSwitch2.13@309.407,221.857 DSwitch2.12@307.32,222.873 ; DSwitch2.13@309.407,222.897 DSwitch2.12@307.32,221.881 ; DSwitch2.4@309.407,229.477 DSwitch2.5@307.32,230.493 ; DSwitch2.4@309.407,230.517 DSwitch2.5@307.32,229.501 ; DSwitch3.13@309.521,192.621 307.287,193.167 DSwitch3.13@309.521,193.713 ; DSwitch3.4@309.521,200.241 307.287,200.787 DSwitch3.4@309.521,201.333 ; DSwitch2.13@309.521,221.831 307.287,222.377 DSwitch2.13@309.521,222.923 ; DSwitch2.4@309.521,229.451 307.287,229.997 DSwitch2.4@309.521,230.543 ; DSwitch.13@309.534,162.167 DSwitch.12@307.447,163.183 ; DSwitch.13@309.534,163.207 DSwitch.12@307.447,162.191 ; DSwitch.4@309.534,169.787 DSwitch.5@307.447,170.803 ; DSwitch.4@309.534,170.827 DSwitch.5@307.447,169.811 ; DSwitch3.13@309.64,192.62 DSwitch3.12@307.32,192.671 ; DSwitch3.13@309.64,193.714 DSwitch3.12@307.32,193.663 ; DSwitch3.4@309.64,200.24 DSwitch3.5@307.32,200.291 ; DSwitch3.4@309.64,201.334 DSwitch3.5@307.32,201.283 ; DSwitch2.13@309.64,221.83 DSwitch2.12@307.32,221.881 ; DSwitch2.13@309.64,222.924 DSwitch2.12@307.32,222.873 ; DSwitch2.4@309.64,229.45 DSwitch2.5@307.32,229.501 ; DSwitch2.4@309.64,230.544 DSwitch2.5@307.32,230.493 ; DSwitch.13@309.648,162.141 307.414,162.687 DSwitch.13@309.648,163.233 ; DSwitch.4@309.648,169.761 307.414,170.307 DSwitch.4@309.648,170.853 ; DSwitch.13@309.767,162.14 DSwitch.12@307.447,162.191 ; DSwitch.13@309.767,163.234 DSwitch.12@307.447,163.183 ; DSwitch.4@309.767,169.76 DSwitch.5@307.447,169.811 ; DSwitch.4@309.767,170.854 DSwitch.5@307.447,170.803 ; DSwitch3.4@310.13,200.874 309.587,202.526 ; DSwitch2.4@310.132,230.075 309.587,231.941 ; DSwitch.4@310.255,170.404 309.714,171.87 ; 7407_4.7@314.541,205.806 315.087,208.04 7407_4.7@315.633,205.806 ; 7407_3.7@314.546,236.502 315.087,235.077 ; 7407_4.7@314.548,205.632 315.087,204.343 ; 7407_2.7@314.673,174.907 315.214,173.482 ; 7407_2.7@314.68,175.138 315.214,176.149 ; 7407_3.7@315.087,236.601 315.087,235.077 ; 7407_4.7@315.626,205.632 315.087,204.343 ; 7407_3.7@315.628,236.502 315.087,235.077 ; 7407_2.7@315.748,175.138 315.214,176.149 ; 7407_2.7@315.755,174.907 315.214,173.482 ; 194.945,195.199 205.994,195.199 207.137,196.342 ; 238.455,114.974 MAX232_2.15@236.474,113.352 236.833,113.352 238.524,115.043 238.524,124.696 LCC_comm.P$9@238.506,124.714 238.524,122.464 ; KANAN.49@264.56,150.253 KANAN.50@266.827,150.749 ; KANAN.49@264.56,151.245 KANAN.50@266.827,150.749 ; KANAN.50@266.827,150.749 267.843,150.749 ; KANAN.50@266.827,150.749 268.986,151.892 ; KANAN.50@266.827,150.749 267.843,150.749 ; 267.843,150.749 266.976,150.22 267.843,150.749 ; 267.843,150.749 266.976,151.278 267.843,150.749 ; 267.843,150.749 268.986,151.892 ; 268.986,151.892 268.986,169.672 271.272,171.958 LLC_SolenoidValve1.P$4@281.305,171.958 LLC_SolenoidValve1.P$9@291.465,171.958 294.132,171.958 295.148,172.974 295.148,176.403 296.926,178.181 313.182,178.181 315.214,176.149 ; 307.047,199.224 DSwitch3.5@307.047,200.787 DSwitch3.4@309.587,200.787 ; 307.047,199.224 DSwitch3.12@307.047,193.167 DSwitch3.13@309.587,193.167 ; 307.174,160.87 DSwitch.12@307.174,162.687 ; DSwitch.12@307.174,162.687 DSwitch.5@307.174,170.307 DSwitch.4@309.714,170.307 ; DSwitch.12@307.174,162.687 DSwitch.13@309.714,162.687 ; DSwitch3.12@307.32,192.671 DSwitch3.13@309.587,193.167 ; DSwitch3.12@307.32,193.663 DSwitch3.13@309.587,193.167 ; DSwitch3.5@307.32,200.291 DSwitch3.4@309.587,200.787 ; DSwitch3.5@307.32,201.283 DSwitch3.4@309.587,200.787 ; DSwitch2.12@307.32,221.881 DSwitch2.13@309.587,222.377 ; DSwitch2.12@307.32,222.873 DSwitch2.13@309.587,222.377 ; DSwitch2.5@307.32,229.501 DSwitch2.4@309.587,229.997 ; DSwitch2.5@307.32,230.493 DSwitch2.4@309.587,229.997 ; DSwitch.12@307.447,162.191 DSwitch.13@309.714,162.687 ; DSwitch.12@307.447,163.183 DSwitch.13@309.714,162.687 ; DSwitch.5@307.447,169.811 DSwitch.4@309.714,170.307 ; DSwitch.5@307.447,170.803 DSwitch.4@309.714,170.307 ; DSwitch3.4@309.587,200.787 309.587,202.526 ; 309.587,202.526 310.261,203.2 313.944,203.2 315.087,204.343 ; DSwitch2.13@309.587,222.377 DSwitch2.12@307.047,222.377 DSwitch2.5@307.047,229.997 DSwitch2.4@309.587,229.997 ; DSwitch2.13@309.587,222.377 309.587,219.241 313.182,215.646 316.357,215.646 317.754,214.249 317.754,212.598 315.087,209.931 7407_4.7@315.087,205.74 315.087,204.343 ; DSwitch2.4@309.587,229.997 309.587,231.941 ; 309.587,231.941 310.896,233.25 313.26,233.25 315.087,235.077 ; DSwitch.4@309.714,170.307 309.714,171.87 ; 309.714,171.87 310.564,172.72 314.452,172.72 315.214,173.482 ; 315.214,173.482 7407_2.7@315.214,175.006 315.214,176.149
  Bottom Layer w1: 10uF.2@202.819,73.192 215.203,73.192 218.58,76.568 ; 7810.2@218.065,80.879 218.58,76.896 ; 7810.2@218.58,80.912 218.58,76.896 ; 7810.2@218.58,81.166 218.58,76.568 ; 7810.2@219.095,80.879 218.58,76.896 ; 100uF.2@232.069,83.947 232.069,79.161 ; PWR_24_IN.2@232.548,67.566 233.566,71.974 PWR_24_IN.2@234.583,67.566 ; PWR_24_IN.2@233.566,67.45 233.566,77.664 232.069,79.161 ; 273.439,80.857 273.952,78.473 ; 273.952,80.912 273.952,78.473 ; 273.952,81.166 273.952,78.473 ; 274.465,80.857 273.952,78.473 ; LLC_SolenoidValve3.P$4@281.178,201.803 LLC_SolenoidValve3.P$9@291.338,201.803 ; 288.417,91.059 294.005,91.059 ; 294.735,230.918 LLC_SolenoidValve2.P$9@291.338,233.299 ; v2(295.148,227.711) 295.148,230.505 292.354,233.299 ; 298.577,91.059 294.005,91.059 ; 307.975,80.264 310.769,80.264 313.309,82.804 can2.1@313.309,86.614 ; 218.58,76.568 220.472,74.676 227.584,74.676 232.069,79.161 ; 273.952,78.473 279.233,73.192 470nF.2@289.941,73.192 291.378,73.192 294.005,75.819 294.005,91.059 ; LLC_SolenoidValve2.P$9@291.338,233.299 292.354,233.299 ; LLC_SolenoidValve2.P$9@291.338,233.299 292.354,233.299
Net1k_2: 1k.2 500.1 KIRI.10 | length 60.7
  Top Layer w0.5: 500.1@198.611,196.908 200.835,197.049 ; 500.1@198.611,197.808 200.835,197.667 ; 500.1@198.674,196.91 200.828,197.358 500.1@198.674,197.806 ; 500.1@198.735,196.921 200.835,197.667 ; 500.1@198.735,197.795 200.835,197.049 ; 1k.2@201.503,196.91 199.349,197.358 ; 1k.2@201.503,197.806 199.349,197.358 ; 1k.2@201.549,197.358 500.1@198.628,197.358 ; 500.1@198.628,197.358 199.349,197.358 ; 500.1@198.628,197.358 200.835,197.049 ; 500.1@198.628,197.358 199.349,197.358 ; 500.1@198.628,197.358 200.835,197.667 ; 199.349,197.358 198.768,196.93 199.349,197.358 ; 199.349,197.358 198.768,197.786 199.349,197.358
  Bottom Layer w0.3: 210.312,200.787 210.312,200.7 210.713,200.299 214.777,200.299 ; KIRI.10@215.491,201.916 214.777,200.299 ; KIRI.10@215.756,201.771 214.777,200.299 ; KIRI.10@216.249,201.278 214.777,200.299 ; KIRI.10@216.394,201.013 214.777,200.299 ; 214.777,200.299 KIRI.10@216.027,201.549 214.777,200.299
  Bottom Layer w0.5: 1k.2@201.101,197.404 201.549,199.558 1k.2@201.997,197.404 ; 1k.2@201.549,197.358 201.549,199.771 202.565,200.787 210.312,200.787
Net1k_2_2: 1k_2.2 500_2.1 KIRI.7 | length 39.3
  Top Layer w0.3: 208.788,203.327 212.725,203.327 KIRI.7@213.487,204.089
  Top Layer w0.5: 500_2.1@204.343,204.978 1k_2.2@207.137,204.978 ; 500_2.1@204.389,204.53 206.543,204.978 500_2.1@204.389,205.426 ; 1k_2.2@206.851,204.631 208.788,203.327 ; 1k_2.2@207.025,204.542 500_2.1@204.922,205.315 ; 1k_2.2@207.025,205.414 500_2.1@204.922,204.641 ; 1k_2.2@207.091,204.53 500_2.1@204.937,204.978 ; 1k_2.2@207.091,205.426 500_2.1@204.937,204.978 ; 1k_2.2@207.16,204.529 500_2.1@204.922,204.641 ; 1k_2.2@207.16,205.427 500_2.1@204.922,205.315 ; 1k_2.2@207.484,205.264 208.788,203.327 ; 500_2.1@204.922,204.641 1k_2.2@207.137,204.978 ; 500_2.1@204.922,205.315 1k_2.2@207.137,204.978 ; 500_2.1@204.937,204.978 1k_2.2@207.137,204.978 ; 1k_2.2@207.137,204.978 208.788,203.327
Net2k2_2: 2k2.2 4k7.1 op-amp1.2 | length 31.4
  Top Layer w0.5: 2k2.2@173.482,124.079 4k7.1@177.165,124.079 177.165,127.127 178.181,128.143 op-amp1.2@181.356,128.143 179.056,128.143 ; 2k2.2@173.528,123.631 175.682,124.079 2k2.2@173.528,124.527 ; 4k7.1@176.717,124.125 177.165,126.279 4k7.1@177.613,124.125 ; 4k7.1@177.119,123.631 174.965,124.079 4k7.1@177.119,124.527 ; op-amp1.2@181.29,127.597 179.056,128.143 ; op-amp1.2@181.29,128.689 179.056,128.143
Net2k2_2_2: 2k2_2.2 4k7_2.1 op-amp1.6 | length 51
  Top Layer w0.5: 4k7_2.1@170.875,106.472 171.323,108.626 4k7_2.1@171.771,106.472 ; 4k7_2.1@171.323,106.426 171.323,110.363 2k2_2.2@175.006,114.046 ; 2k2_2.2@174.66,114.334 173.245,112.285 ; 2k2_2.2@175.053,113.598 177.165,114.046 ; 2k2_2.2@175.053,114.494 177.165,114.046 ; 2k2_2.2@175.294,113.7 173.245,112.285 ; op-amp1.6@188.868,125.064 187.579,125.603 ; op-amp1.6@188.868,126.142 187.579,125.603 ; 173.245,112.285 2k2_2.2@175.006,114.046 ; 2k2_2.2@175.006,114.046 177.165,114.046 ; 177.165,114.046 178.943,115.824 178.943,117.348 181.737,120.142 185.166,120.142 186.817,121.793 186.817,124.841 187.579,125.603 ; 187.579,125.603 op-amp1.6@188.976,125.603 187.579,125.603
Net4k7_2: 4k7.2 10k.1 op-amp1.1 | length 36.7
  Top Layer w0.5: 10k.1@169.224,124.125 169.672,126.279 10k.1@170.12,124.125 ; 10k.1@169.672,124.079 169.672,126.365 171.45,128.143 176.276,128.143 177.165,129.032 4k7.2@177.165,131.699 178.181,130.683 ; 4k7.2@176.717,131.653 177.165,129.499 4k7.2@177.613,131.653 ; 4k7.2@176.901,131.335 178.181,130.683 ; 4k7.2@177.529,131.963 178.181,130.683 ; op-amp1.1@181.29,130.137 179.056,130.683 ; op-amp1.1@181.29,131.229 179.056,130.683 ; 178.181,130.683 op-amp1.1@181.356,130.683 179.056,130.683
